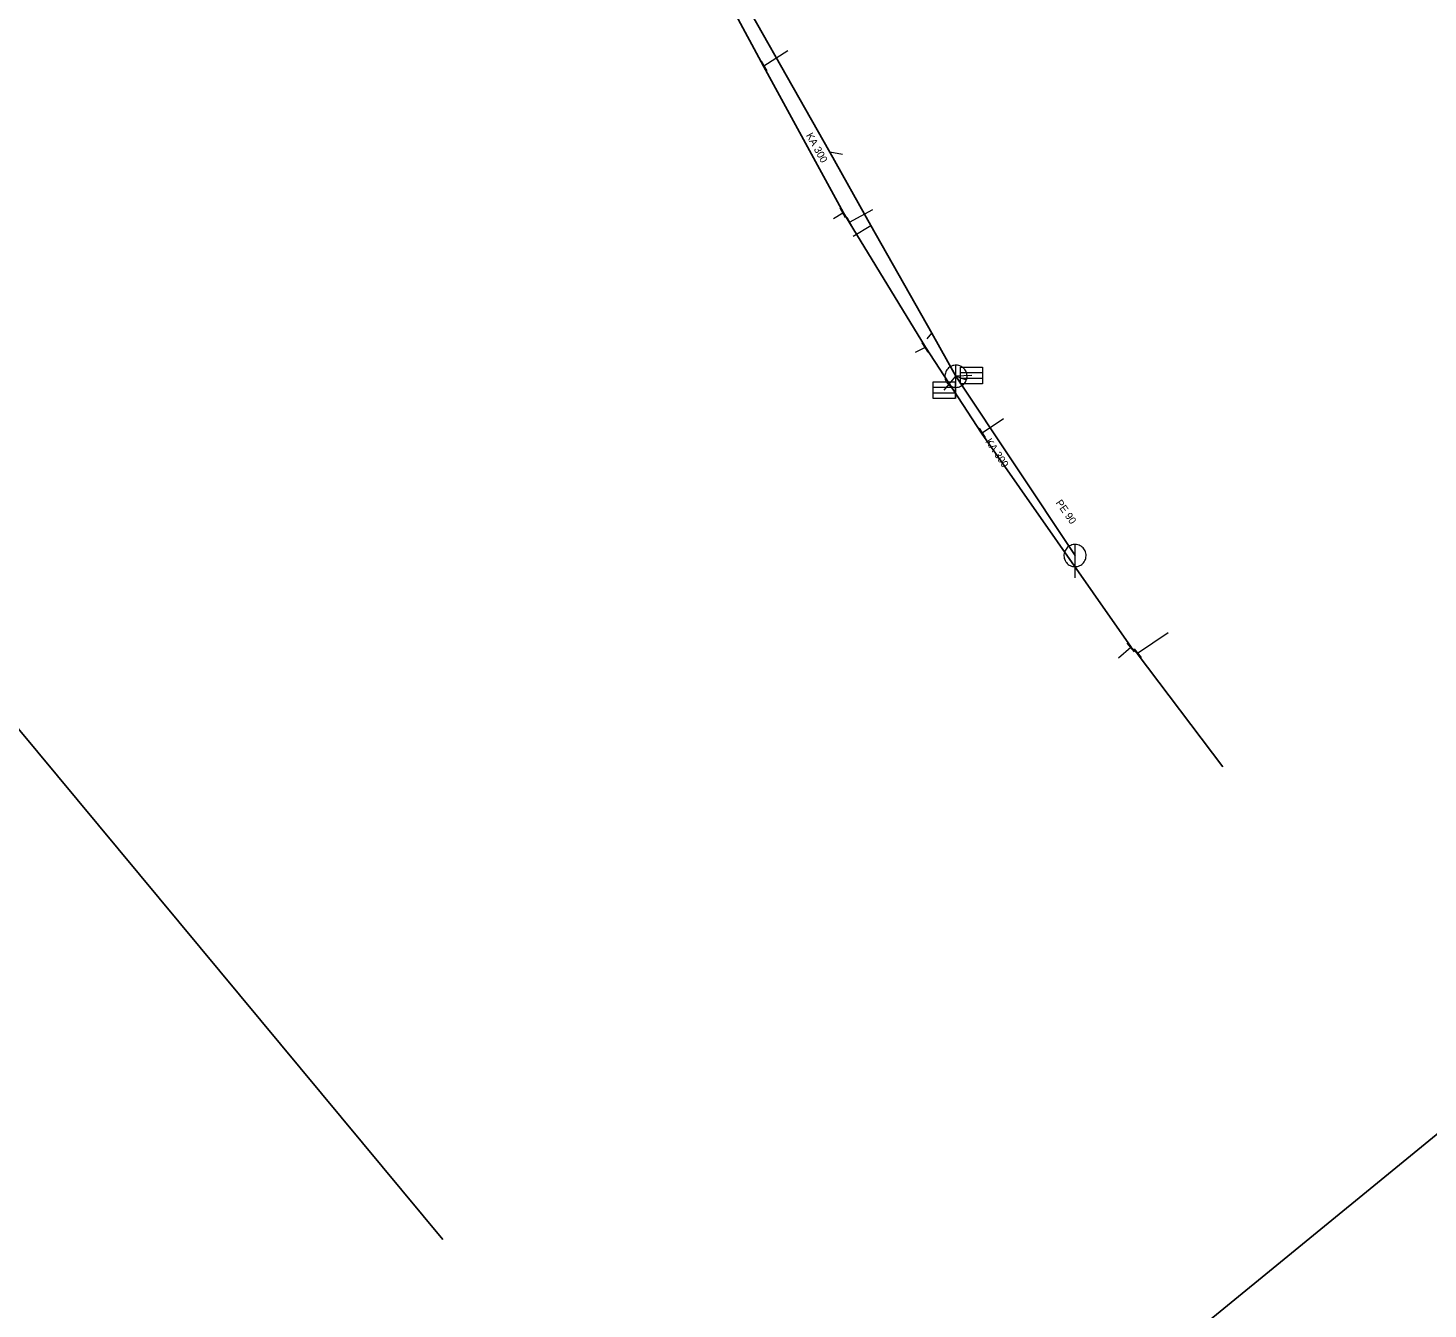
# Model space of a CAD drawing. Extents: x -688432 to -687974, y -973332 to -972704.
# Drawn here: x -688275.2 to -688148.9, y -973102.6 to -972987.1 of the extents above; entities that cross this region are included whole.
import ezdxf
from ezdxf.enums import TextEntityAlignment as Align

# ---------------------------------------------------------------- set-up
doc = ezdxf.new("R2010")
doc.units = 0
doc.header["$LTSCALE"] = 0.27
for name, color, linetype, lineweight in [('1', 7, 'Continuous', 25), ('11', 7, 'Continuous', 13), ('13', 7, 'Continuous', 13), ('14', 7, 'Continuous', 25), ('17', 7, 'Continuous', 25), ('22', 7, 'Continuous', 13), ('34', 7, 'Continuous', 13)]:
    doc.layers.add(name, color=color, linetype=linetype, lineweight=lineweight)

msp = doc.modelspace()

# ---------------------------------------------------------------- linework, layer by layer
at = {"layer": '11'}
for p, q in [((-688201.73, -972998.51), (-688202.881, -972998.296)), ((-688200.76, -973005.87), (-688199.167, -973004.908)), ((-688194.088, -973015.125), (-688193.675, -973014.629)), ((-688192.539, -973019.75), (-688191.489, -973018.5)), ((-688190.07, -973018.43), (-688191.489, -973018.5)), ((-688190.537, -973018.848), (-688191.489, -973018.5))]:
    msp.add_line(p, q, dxfattribs=at)
at = {"layer": '13'}
for p, q in [((-688208.809, -972990.516), (-688206.66, -972989.129)), ((-688201.686, -973003.785), (-688202.53, -973004.309)), ((-688201.085, -973004.591), (-688198.98, -973003.46)), ((-688194.281, -973015.906), (-688195.16, -973016.359)), ((-688189.139, -973023.594), (-688187.199, -973022.309)), ((-688175.111, -973043.479), (-688172.34, -973041.61)), ((-688175.719, -973042.962), (-688176.84, -973043.93))]:
    msp.add_line(p, q, dxfattribs=at)
at = {"layer": '14', "lineweight": 13}
for p, q in [((-688208.85, -972990.539), (-688208.809, -972990.516)), ((-688201.64, -973003.76), (-688201.686, -973003.785)), ((-688201.127, -973004.614), (-688201.085, -973004.591)), ((-688194.239, -973015.879), (-688194.281, -973015.906)), ((-688189.18, -973023.62), (-688189.139, -973023.594)), ((-688175.68, -973042.93), (-688175.719, -973042.962)), ((-688175.149, -973043.51), (-688175.111, -973043.479))]:
    msp.add_line(p, q, dxfattribs=at)
at = {"layer": '14'}
msp.add_line((-688180.75, -973034.67), (-688191.489, -973018.5), dxfattribs=at)
msp.add_lwpolyline([(-688191.489, -973018.5), (-688193.675, -973014.629), (-688199.167, -973004.908), (-688202.881, -972998.296), (-688213.289, -972979.879), (-688223.6, -972959.23)], dxfattribs=at)
at = {"layer": '17'}
msp.add_line((-688237.776, -973096.338), (-688295.678, -973026.728), dxfattribs=at)
for points in [[(-688123.609, -972815.609), (-688135.91, -972839.761), (-688146.524, -972867.704), (-688149.164, -972878.87), (-688150.368, -972974.473), (-688134.778, -973051.136), (-688125.903, -973068.701), (-688203.651, -973132.27), (-688148.612, -973199.748), (-688078.631, -973291.807), (-688049.631, -973331.642)], [(-688167.42, -973053.719), (-688175.149, -973043.51), (-688175.68, -973042.93), (-688189.18, -973023.62), (-688194.239, -973015.879), (-688201.127, -973004.614), (-688201.64, -973003.76), (-688208.85, -972990.539), (-688214.25, -972980.469), (-688218.649, -972971.53), (-688218.84, -972971.059), (-688222.559, -972963.52), (-688226.68, -972954.28), (-688230.09, -972945.899), (-688231.09, -972942.949), (-688233.719, -972935.719), (-688236.539, -972928.36), (-688237.969, -972924.559)]]:
    msp.add_lwpolyline(points, dxfattribs=at)
at = {"layer": '22'}
for p, q in [((-688191.489, -973020.5), (-688191.488, -973017.5)), ((-688191.081, -973018.173), (-688189.081, -973018.173)), ((-688191.081, -973018.673), (-688189.081, -973018.673)), ((-688193.55, -973019.493), (-688191.55, -973019.493)), ((-688193.55, -973019.993), (-688191.55, -973019.993)), ((-688180.75, -973036.67), (-688180.749, -973033.67))]:
    msp.add_line(p, q, dxfattribs=at)
for points in [[(-688190.489, -973018.5), (-688190.494, -973018.391), (-688190.512, -973018.283), (-688190.542, -973018.177), (-688190.582, -973018.076), (-688190.634, -973017.979), (-688190.696, -973017.889), (-688190.768, -973017.806), (-688190.848, -973017.732), (-688190.936, -973017.666), (-688191.03, -973017.611), (-688191.13, -973017.566), (-688191.235, -973017.533), (-688191.342, -973017.511), (-688191.451, -973017.501), (-688191.561, -973017.503), (-688191.669, -973017.517), (-688191.776, -973017.542), (-688191.879, -973017.579), (-688191.977, -973017.628), (-688192.069, -973017.686), (-688192.155, -973017.755), (-688192.232, -973017.832), (-688192.301, -973017.918), (-688192.36, -973018.01), (-688192.408, -973018.108), (-688192.445, -973018.211), (-688192.471, -973018.318), (-688192.485, -973018.426), (-688192.488, -973018.536), (-688192.478, -973018.645), (-688192.457, -973018.752), (-688192.423, -973018.856), (-688192.379, -973018.956), (-688192.324, -973019.051), (-688192.258, -973019.139), (-688192.184, -973019.219), (-688192.101, -973019.291), (-688192.011, -973019.353), (-688191.915, -973019.405), (-688191.813, -973019.446), (-688191.708, -973019.476), (-688191.6, -973019.494), (-688191.49, -973019.5), (-688191.381, -973019.494), (-688191.273, -973019.476), (-688191.168, -973019.447), (-688191.066, -973019.406), (-688190.969, -973019.354), (-688190.879, -973019.292), (-688190.796, -973019.221), (-688190.721, -973019.141), (-688190.656, -973019.053), (-688190.6, -973018.959), (-688190.556, -973018.859), (-688190.522, -973018.755), (-688190.5, -973018.647), (-688190.49, -973018.538)], [(-688191.081, -973017.673), (-688189.081, -973017.673), (-688189.081, -973019.173), (-688191.081, -973019.173)], [(-688193.55, -973018.993), (-688191.55, -973018.993), (-688191.55, -973020.493), (-688193.55, -973020.493)], [(-688179.75, -973034.67), (-688179.755, -973034.561), (-688179.773, -973034.453), (-688179.803, -973034.347), (-688179.843, -973034.246), (-688179.895, -973034.149), (-688179.957, -973034.059), (-688180.029, -973033.976), (-688180.109, -973033.902), (-688180.197, -973033.836), (-688180.291, -973033.781), (-688180.391, -973033.736), (-688180.496, -973033.703), (-688180.603, -973033.681), (-688180.712, -973033.671), (-688180.822, -973033.673), (-688180.93, -973033.687), (-688181.037, -973033.712), (-688181.14, -973033.749), (-688181.238, -973033.798), (-688181.33, -973033.856), (-688181.416, -973033.925), (-688181.493, -973034.002), (-688181.562, -973034.088), (-688181.621, -973034.18), (-688181.669, -973034.278), (-688181.706, -973034.381), (-688181.732, -973034.488), (-688181.746, -973034.596), (-688181.749, -973034.706), (-688181.739, -973034.815), (-688181.718, -973034.922), (-688181.684, -973035.026), (-688181.64, -973035.126), (-688181.585, -973035.221), (-688181.519, -973035.309), (-688181.445, -973035.389), (-688181.362, -973035.461), (-688181.272, -973035.523), (-688181.176, -973035.575), (-688181.074, -973035.616), (-688180.969, -973035.646), (-688180.861, -973035.664), (-688180.751, -973035.67), (-688180.642, -973035.664), (-688180.534, -973035.646), (-688180.429, -973035.617), (-688180.327, -973035.576), (-688180.23, -973035.524), (-688180.14, -973035.462), (-688180.057, -973035.391), (-688179.982, -973035.311), (-688179.917, -973035.223), (-688179.861, -973035.129), (-688179.817, -973035.029), (-688179.783, -973034.925), (-688179.761, -973034.817), (-688179.751, -973034.708)]]:
    msp.add_lwpolyline(points, close=True, dxfattribs=at)
at = {"layer": '34'}
for p, q in [((-688209.059, -972990.083), (-688208.559, -972990.949)), ((-688201.448, -973004.224), (-688201.922, -973003.344)), ((-688201.323, -973004.151), (-688200.847, -973005.031)), ((-688194.01, -973016.326), (-688194.55, -973015.485)), ((-688189.41, -973023.174), (-688188.868, -973024.014)), ((-688175.399, -973043.346), (-688176.037, -973042.576)), ((-688175.426, -973043.09), (-688174.796, -973043.867))]:
    msp.add_line(p, q, dxfattribs=at)

# ---------------------------------------------------------------- texts
at = {"layer": '1'}
for s, rotation, p in [('KA 300', 299, (-688204.3232, -972998.0485)), ('KA 300', 299, (-688204.3232, -972998.0485)), ('KA 300', 299, (-688204.3232, -972998.0485)), ('KA 300', 299, (-688204.3232, -972998.0485)), ('KA 300', 299, (-688204.3232, -972998.0485)), ('KA 300', 304, (-688188.0553, -973025.5977)), ('KA 300', 304, (-688188.0553, -973025.5977)), ('KA 300', 304, (-688188.0553, -973025.5977)), ('KA 300', 304, (-688188.0553, -973025.5977)), ('KA 300', 304, (-688188.0553, -973025.5977)), ('PE 90 ', 305, (-688181.7543, -973031.012)), ('PE 90 ', 305, (-688181.7543, -973031.012)), ('PE 90 ', 305, (-688181.7543, -973031.012)), ('PE 90 ', 305, (-688181.7543, -973031.012)), ('PE 90 ', 305, (-688181.7543, -973031.012))]:
    msp.add_text(s, height=0.6667, rotation=rotation, dxfattribs=at).set_placement(p, align=Align.CENTER)

doc.saveas('drawing.dxf')
